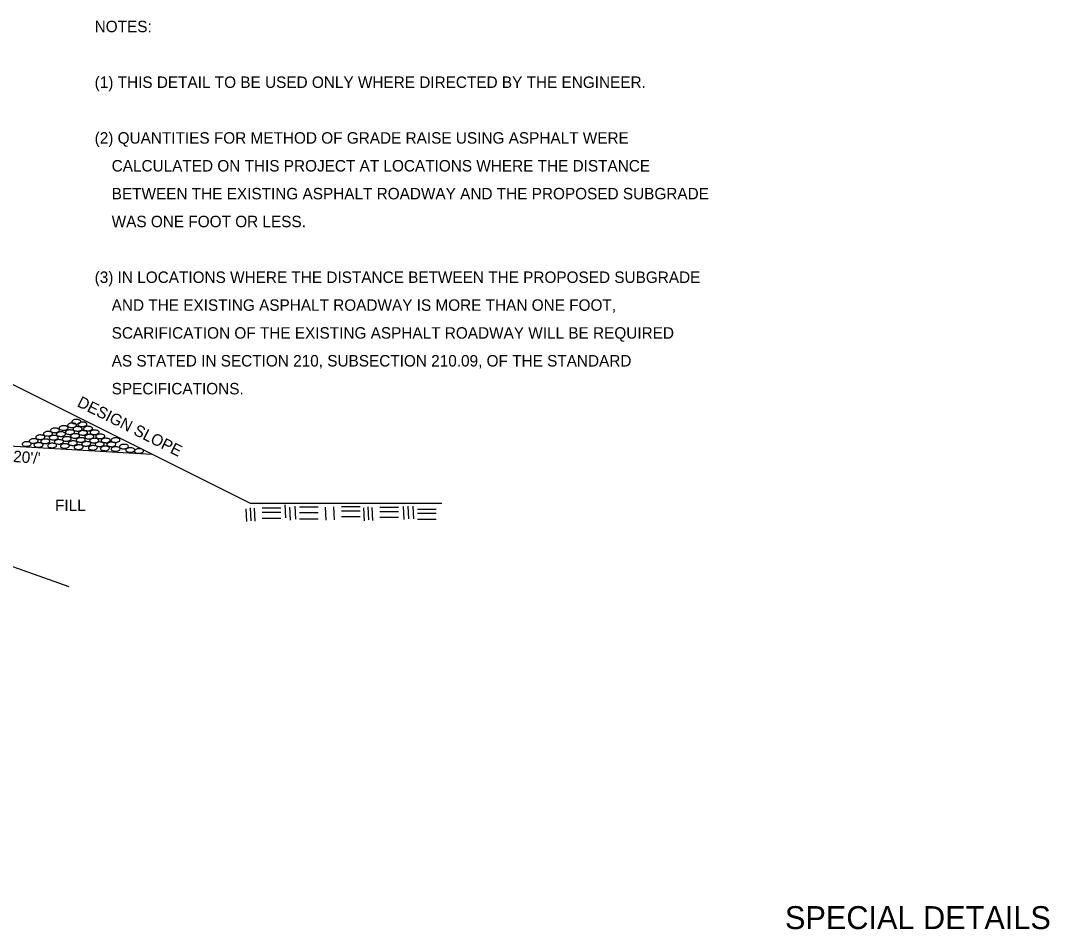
# Model space of a CAD drawing. Extents: x 1955771 to 1955918, y 566326 to 566544.
# Drawn here: x 1955864 to 1955917.8, y 566445.7 to 566493.2 of the extents above; entities that cross this region are included whole.
import ezdxf

# ---------------------------------------------------------------- set-up
doc = ezdxf.new("R2010")
doc.units = 0
doc.layers.add('R_Border', color=7, linetype='Continuous')
doc.layers.add('R_Logo', color=7, linetype='Continuous')

msp = doc.modelspace()

# ---------------------------------------------------------------- linework, layer by layer
at = {"layer": 'R_Logo'}
for p, q in [((1955876.008, 566467.953), (1955863.589, 566474.161)), ((1955855.453, 566471.441), (1955870.832, 566470.54)), ((1955849.109, 566469.803), (1955866.493, 566463.617)), ((1955886.016, 566467.953), (1955876.008, 566467.953)), ((1955877.804, 566467.882), (1955877.84, 566467.206)), ((1955878.033, 566467.767), (1955878.071, 566467.09)), ((1955878.322, 566467.826), (1955878.359, 566467.148)), ((1955879.546, 566467.769), (1955878.562, 566467.769)), ((1955879.908, 566467.76), (1955879.948, 566467.083)), ((1955880.343, 566467.784), (1955880.381, 566467.108)), ((1955881.736, 566467.784), (1955880.758, 566467.784)), ((1955882.146, 566467.778), (1955882.182, 566467.1)), ((1955882.348, 566467.754), (1955882.386, 566467.076)), ((1955883.741, 566467.754), (1955882.763, 566467.754)), ((1955883.989, 566467.802), (1955884.026, 566467.126)), ((1955884.231, 566467.828), (1955884.269, 566467.152)), ((1955884.488, 566467.828), (1955884.526, 566467.152)), ((1955875.754, 566467.687), (1955875.793, 566467.009)), ((1955875.987, 566467.732), (1955876.026, 566467.055)), ((1955876.19, 566467.71), (1955876.226, 566467.033)), ((1955877.583, 566467.71), (1955876.603, 566467.71)), ((1955877.583, 566467.485), (1955876.603, 566467.485)), ((1955879.546, 566467.478), (1955878.562, 566467.478)), ((1955881.736, 566467.558), (1955880.758, 566467.558)), ((1955881.736, 566467.256), (1955880.758, 566467.256)), ((1955881.912, 566467.73), (1955881.951, 566467.054)), ((1955883.741, 566467.53), (1955882.763, 566467.53)), ((1955883.741, 566467.228), (1955882.763, 566467.228)), ((1955885.717, 566467.652), (1955884.738, 566467.652)), ((1955885.717, 566467.429), (1955884.738, 566467.429)), ((1955877.583, 566467.183), (1955876.603, 566467.183)), ((1955879.546, 566467.133), (1955878.562, 566467.133)), ((1955885.717, 566467.125), (1955884.738, 566467.125))]:
    msp.add_line(p, q, dxfattribs=at)
for points in [[(1955866.663, 566471.931), (1955866.581, 566471.941), (1955866.481, 566471.967), (1955866.433, 566472.013), (1955866.426, 566472.042), (1955866.452, 566472.091), (1955866.478, 566472.115), (1955866.534, 566472.147), (1955866.612, 566472.166), (1955866.655, 566472.166), (1955866.717, 566472.16), (1955866.788, 566472.156), (1955866.84, 566472.135), (1955866.887, 566472.089), (1955866.896, 566472.06), (1955866.881, 566472.012), (1955866.844, 566471.984), (1955866.807, 566471.964), (1955866.749, 566471.942), (1955866.717, 566471.932), (1955866.663, 566471.931)], [(1955866.887, 566472.117), (1955866.804, 566472.127), (1955866.707, 566472.152), (1955866.659, 566472.202), (1955866.652, 566472.228), (1955866.676, 566472.279), (1955866.7, 566472.302), (1955866.757, 566472.332), (1955866.837, 566472.352), (1955866.879, 566472.352), (1955866.942, 566472.349), (1955867.01, 566472.344), (1955867.063, 566472.317), (1955867.116, 566472.277), (1955867.124, 566472.241), (1955867.109, 566472.199), (1955867.07, 566472.166), (1955867.032, 566472.152), (1955866.976, 566472.131), (1955866.942, 566472.118), (1955866.887, 566472.117)], [(1955867.205, 566471.982), (1955867.124, 566471.992), (1955867.023, 566472.016), (1955866.974, 566472.065), (1955866.967, 566472.09), (1955866.993, 566472.144), (1955867.021, 566472.164), (1955867.076, 566472.195), (1955867.154, 566472.217), (1955867.195, 566472.217), (1955867.26, 566472.211), (1955867.328, 566472.207), (1955867.382, 566472.181), (1955867.43, 566472.14), (1955867.439, 566472.105), (1955867.423, 566472.064), (1955867.387, 566472.029), (1955867.347, 566472.013), (1955867.293, 566471.995), (1955867.26, 566471.984), (1955867.205, 566471.982)], [(1955865.004, 566471.307), (1955864.92, 566471.317), (1955864.824, 566471.344), (1955864.777, 566471.392), (1955864.768, 566471.419), (1955864.793, 566471.471), (1955864.816, 566471.493), (1955864.873, 566471.522), (1955864.954, 566471.545), (1955864.995, 566471.545), (1955865.056, 566471.54), (1955865.127, 566471.534), (1955865.179, 566471.508), (1955865.232, 566471.467), (1955865.239, 566471.433), (1955865.224, 566471.389), (1955865.185, 566471.357), (1955865.15, 566471.342), (1955865.092, 566471.321), (1955865.056, 566471.309), (1955865.004, 566471.307)], [(1955865.406, 566471.488), (1955865.321, 566471.496), (1955865.223, 566471.523), (1955865.17, 566471.568), (1955865.165, 566471.598), (1955865.188, 566471.647), (1955865.22, 566471.671), (1955865.278, 566471.706), (1955865.356, 566471.721), (1955865.396, 566471.721), (1955865.457, 566471.718), (1955865.528, 566471.711), (1955865.58, 566471.691), (1955865.629, 566471.643), (1955865.635, 566471.615), (1955865.619, 566471.567), (1955865.582, 566471.539), (1955865.547, 566471.519), (1955865.495, 566471.502), (1955865.461, 566471.493), (1955865.406, 566471.488)], [(1955865.706, 566471.281), (1955865.619, 566471.292), (1955865.523, 566471.318), (1955865.474, 566471.365), (1955865.468, 566471.394), (1955865.493, 566471.444), (1955865.516, 566471.469), (1955865.575, 566471.497), (1955865.653, 566471.516), (1955865.694, 566471.516), (1955865.758, 566471.513), (1955865.828, 566471.508), (1955865.88, 566471.485), (1955865.931, 566471.44), (1955865.938, 566471.411), (1955865.922, 566471.361), (1955865.885, 566471.335), (1955865.846, 566471.317), (1955865.791, 566471.295), (1955865.758, 566471.282), (1955865.706, 566471.281)], [(1955865.764, 566471.661), (1955865.681, 566471.67), (1955865.582, 566471.704), (1955865.534, 566471.745), (1955865.525, 566471.775), (1955865.552, 566471.825), (1955865.58, 566471.851), (1955865.632, 566471.879), (1955865.711, 566471.898), (1955865.755, 566471.898), (1955865.817, 566471.901), (1955865.885, 566471.887), (1955865.941, 566471.862), (1955865.99, 566471.821), (1955865.997, 566471.789), (1955865.985, 566471.742), (1955865.945, 566471.71), (1955865.91, 566471.698), (1955865.85, 566471.678), (1955865.817, 566471.666), (1955865.764, 566471.661)], [(1955866.086, 566471.466), (1955866.003, 566471.475), (1955865.906, 566471.502), (1955865.855, 566471.55), (1955865.846, 566471.574), (1955865.873, 566471.63), (1955865.903, 566471.653), (1955865.953, 566471.685), (1955866.034, 566471.704), (1955866.077, 566471.704), (1955866.139, 566471.705), (1955866.21, 566471.694), (1955866.263, 566471.666), (1955866.312, 566471.627), (1955866.319, 566471.594), (1955866.305, 566471.548), (1955866.268, 566471.514), (1955866.229, 566471.498), (1955866.172, 566471.483), (1955866.139, 566471.471), (1955866.086, 566471.466)], [(1955866.225, 566471.789), (1955866.139, 566471.798), (1955866.041, 566471.827), (1955865.99, 566471.872), (1955865.985, 566471.903), (1955866.01, 566471.953), (1955866.037, 566471.977), (1955866.092, 566472.005), (1955866.172, 566472.024), (1955866.215, 566472.024), (1955866.278, 566472.021), (1955866.348, 566472.017), (1955866.398, 566471.994), (1955866.447, 566471.949), (1955866.455, 566471.919), (1955866.439, 566471.87), (1955866.401, 566471.842), (1955866.364, 566471.826), (1955866.311, 566471.803), (1955866.278, 566471.79), (1955866.225, 566471.789)], [(1955866.558, 566471.569), (1955866.473, 566471.58), (1955866.373, 566471.609), (1955866.32, 566471.653), (1955866.315, 566471.683), (1955866.342, 566471.732), (1955866.369, 566471.757), (1955866.43, 566471.788), (1955866.507, 566471.806), (1955866.547, 566471.806), (1955866.61, 566471.803), (1955866.678, 566471.795), (1955866.734, 566471.776), (1955866.779, 566471.728), (1955866.788, 566471.701), (1955866.772, 566471.651), (1955866.735, 566471.625), (1955866.698, 566471.605), (1955866.646, 566471.587), (1955866.612, 566471.576), (1955866.558, 566471.569)], [(1955866.824, 566471.373), (1955866.741, 566471.382), (1955866.643, 566471.411), (1955866.594, 566471.456), (1955866.588, 566471.485), (1955866.612, 566471.536), (1955866.636, 566471.559), (1955866.694, 566471.587), (1955866.773, 566471.609), (1955866.814, 566471.609), (1955866.877, 566471.605), (1955866.947, 566471.599), (1955867, 566471.573), (1955867.052, 566471.531), (1955867.057, 566471.498), (1955867.044, 566471.453), (1955867.006, 566471.423), (1955866.968, 566471.409), (1955866.912, 566471.386), (1955866.877, 566471.374), (1955866.824, 566471.373)], [(1955866.959, 566471.744), (1955866.872, 566471.753), (1955866.774, 566471.779), (1955866.723, 566471.827), (1955866.717, 566471.854), (1955866.742, 566471.907), (1955866.77, 566471.928), (1955866.826, 566471.958), (1955866.906, 566471.98), (1955866.948, 566471.98), (1955867.01, 566471.974), (1955867.08, 566471.97), (1955867.131, 566471.942), (1955867.181, 566471.903), (1955867.189, 566471.867), (1955867.173, 566471.825), (1955867.134, 566471.791), (1955867.099, 566471.778), (1955867.044, 566471.757), (1955867.01, 566471.745), (1955866.959, 566471.744)], [(1955867.238, 566471.531), (1955867.154, 566471.543), (1955867.055, 566471.567), (1955867.006, 566471.616), (1955866.998, 566471.642), (1955867.023, 566471.696), (1955867.052, 566471.715), (1955867.109, 566471.748), (1955867.188, 566471.77), (1955867.229, 566471.77), (1955867.29, 566471.763), (1955867.361, 566471.759), (1955867.412, 566471.733), (1955867.463, 566471.692), (1955867.471, 566471.657), (1955867.456, 566471.615), (1955867.416, 566471.583), (1955867.381, 566471.564), (1955867.324, 566471.548), (1955867.29, 566471.534), (1955867.238, 566471.531)], [(1955867.505, 566471.761), (1955867.417, 566471.77), (1955867.322, 566471.792), (1955867.268, 566471.843), (1955867.263, 566471.869), (1955867.289, 566471.921), (1955867.318, 566471.942), (1955867.374, 566471.975), (1955867.454, 566471.996), (1955867.493, 566471.996), (1955867.557, 566471.992), (1955867.626, 566471.987), (1955867.679, 566471.96), (1955867.725, 566471.919), (1955867.734, 566471.886), (1955867.719, 566471.841), (1955867.683, 566471.809), (1955867.645, 566471.791), (1955867.59, 566471.775), (1955867.557, 566471.763), (1955867.505, 566471.761)], [(1955867.558, 566471.571), (1955867.645, 566471.562), (1955867.743, 566471.536), (1955867.795, 566471.488), (1955867.801, 566471.46), (1955867.776, 566471.412), (1955867.747, 566471.387), (1955867.689, 566471.356), (1955867.611, 566471.337), (1955867.569, 566471.337), (1955867.508, 566471.342), (1955867.437, 566471.345), (1955867.386, 566471.369), (1955867.337, 566471.414), (1955867.33, 566471.444), (1955867.344, 566471.49), (1955867.384, 566471.519), (1955867.417, 566471.539), (1955867.474, 566471.559), (1955867.508, 566471.568), (1955867.558, 566471.571)], [(1955867.835, 566471.803), (1955867.916, 566471.792), (1955868.016, 566471.77), (1955868.069, 566471.72), (1955868.076, 566471.695), (1955868.052, 566471.641), (1955868.022, 566471.622), (1955867.964, 566471.585), (1955867.886, 566471.567), (1955867.844, 566471.567), (1955867.784, 566471.573), (1955867.712, 566471.577), (1955867.659, 566471.602), (1955867.613, 566471.644), (1955867.607, 566471.678), (1955867.622, 566471.721), (1955867.655, 566471.754), (1955867.692, 566471.773), (1955867.747, 566471.788), (1955867.782, 566471.801), (1955867.835, 566471.803)], [(1955868.136, 566471.593), (1955868.22, 566471.584), (1955868.319, 566471.559), (1955868.372, 566471.509), (1955868.378, 566471.484), (1955868.352, 566471.431), (1955868.325, 566471.411), (1955868.266, 566471.375), (1955868.19, 566471.357), (1955868.146, 566471.357), (1955868.083, 566471.361), (1955868.011, 566471.366), (1955867.962, 566471.393), (1955867.913, 566471.433), (1955867.907, 566471.469), (1955867.923, 566471.512), (1955867.958, 566471.545), (1955867.994, 566471.56), (1955868.051, 566471.577), (1955868.081, 566471.591), (1955868.136, 566471.593)], [(1955864.288, 566470.952), (1955864.205, 566470.959), (1955864.108, 566470.984), (1955864.061, 566471.034), (1955864.052, 566471.06), (1955864.079, 566471.114), (1955864.103, 566471.135), (1955864.159, 566471.167), (1955864.239, 566471.187), (1955864.279, 566471.187), (1955864.344, 566471.183), (1955864.414, 566471.177), (1955864.468, 566471.152), (1955864.515, 566471.111), (1955864.524, 566471.077), (1955864.508, 566471.032), (1955864.474, 566471.001), (1955864.431, 566470.982), (1955864.377, 566470.964), (1955864.344, 566470.954), (1955864.288, 566470.952)], [(1955864.657, 566471.114), (1955864.572, 566471.12), (1955864.478, 566471.148), (1955864.426, 566471.194), (1955864.42, 566471.223), (1955864.446, 566471.274), (1955864.472, 566471.297), (1955864.527, 566471.328), (1955864.605, 566471.348), (1955864.647, 566471.348), (1955864.712, 566471.344), (1955864.783, 566471.34), (1955864.832, 566471.314), (1955864.883, 566471.272), (1955864.892, 566471.239), (1955864.876, 566471.193), (1955864.84, 566471.164), (1955864.799, 566471.146), (1955864.742, 566471.124), (1955864.712, 566471.114), (1955864.657, 566471.114)], [(1955864.912, 566470.903), (1955864.826, 566470.911), (1955864.728, 566470.938), (1955864.679, 566470.984), (1955864.671, 566471.014), (1955864.701, 566471.065), (1955864.721, 566471.089), (1955864.783, 566471.117), (1955864.86, 566471.137), (1955864.9, 566471.137), (1955864.964, 566471.133), (1955865.033, 566471.128), (1955865.086, 566471.105), (1955865.137, 566471.06), (1955865.146, 566471.03), (1955865.128, 566470.981), (1955865.092, 566470.955), (1955865.055, 566470.937), (1955864.996, 566470.914), (1955864.964, 566470.904), (1955864.912, 566470.903)], [(1955865.266, 566471.095), (1955865.181, 566471.103), (1955865.086, 566471.128), (1955865.037, 566471.177), (1955865.029, 566471.204), (1955865.055, 566471.256), (1955865.079, 566471.277), (1955865.136, 566471.309), (1955865.216, 566471.33), (1955865.254, 566471.33), (1955865.319, 566471.326), (1955865.388, 566471.321), (1955865.442, 566471.295), (1955865.493, 566471.252), (1955865.501, 566471.22), (1955865.485, 566471.175), (1955865.447, 566471.144), (1955865.41, 566471.126), (1955865.356, 566471.108), (1955865.319, 566471.096), (1955865.266, 566471.095)], [(1955865.621, 566470.874), (1955865.537, 566470.883), (1955865.44, 566470.909), (1955865.391, 566470.958), (1955865.385, 566470.982), (1955865.41, 566471.037), (1955865.435, 566471.057), (1955865.491, 566471.09), (1955865.57, 566471.111), (1955865.611, 566471.111), (1955865.676, 566471.107), (1955865.744, 566471.101), (1955865.796, 566471.075), (1955865.846, 566471.034), (1955865.855, 566470.999), (1955865.842, 566470.955), (1955865.802, 566470.922), (1955865.766, 566470.908), (1955865.707, 566470.888), (1955865.676, 566470.874), (1955865.621, 566470.874)], [(1955865.982, 566471.061), (1955865.895, 566471.072), (1955865.795, 566471.101), (1955865.744, 566471.145), (1955865.735, 566471.175), (1955865.762, 566471.225), (1955865.791, 566471.248), (1955865.848, 566471.28), (1955865.927, 566471.298), (1955865.969, 566471.298), (1955866.03, 566471.296), (1955866.1, 566471.289), (1955866.154, 566471.267), (1955866.201, 566471.221), (1955866.21, 566471.191), (1955866.193, 566471.144), (1955866.155, 566471.114), (1955866.119, 566471.097), (1955866.067, 566471.081), (1955866.033, 566471.068), (1955865.982, 566471.061)], [(1955866.285, 566471.082), (1955866.365, 566471.081), (1955866.466, 566471.045), (1955866.515, 566470.999), (1955866.523, 566470.972), (1955866.498, 566470.918), (1955866.467, 566470.899), (1955866.415, 566470.871), (1955866.332, 566470.849), (1955866.291, 566470.845), (1955866.229, 566470.85), (1955866.161, 566470.864), (1955866.109, 566470.885), (1955866.06, 566470.922), (1955866.053, 566470.957), (1955866.067, 566471.001), (1955866.105, 566471.032), (1955866.14, 566471.054), (1955866.195, 566471.072), (1955866.231, 566471.081), (1955866.285, 566471.082)], [(1955866.388, 566471.219), (1955866.305, 566471.228), (1955866.208, 566471.258), (1955866.158, 566471.302), (1955866.15, 566471.33), (1955866.176, 566471.38), (1955866.205, 566471.409), (1955866.256, 566471.435), (1955866.337, 566471.453), (1955866.378, 566471.453), (1955866.439, 566471.456), (1955866.51, 566471.444), (1955866.564, 566471.42), (1955866.614, 566471.375), (1955866.621, 566471.348), (1955866.607, 566471.298), (1955866.569, 566471.27), (1955866.531, 566471.252), (1955866.475, 566471.236), (1955866.439, 566471.223), (1955866.388, 566471.219)], [(1955866.697, 566471.231), (1955866.781, 566471.229), (1955866.881, 566471.194), (1955866.93, 566471.148), (1955866.938, 566471.118), (1955866.912, 566471.068), (1955866.882, 566471.045), (1955866.828, 566471.02), (1955866.744, 566470.997), (1955866.705, 566470.993), (1955866.643, 566471.001), (1955866.576, 566471.013), (1955866.522, 566471.034), (1955866.473, 566471.072), (1955866.466, 566471.105), (1955866.481, 566471.149), (1955866.519, 566471.179), (1955866.553, 566471.204), (1955866.61, 566471.221), (1955866.645, 566471.229), (1955866.697, 566471.231)], [(1955867.006, 566471.029), (1955867.089, 566471.019), (1955867.188, 566470.985), (1955867.237, 566470.944), (1955867.245, 566470.914), (1955867.217, 566470.866), (1955867.189, 566470.839), (1955867.134, 566470.808), (1955867.055, 566470.79), (1955867.014, 566470.79), (1955866.951, 566470.789), (1955866.882, 566470.799), (1955866.828, 566470.825), (1955866.779, 566470.868), (1955866.772, 566470.897), (1955866.788, 566470.946), (1955866.824, 566470.976), (1955866.862, 566470.992), (1955866.919, 566471.01), (1955866.951, 566471.022), (1955867.006, 566471.029)], [(1955867.114, 566471.402), (1955867.195, 566471.399), (1955867.298, 566471.363), (1955867.345, 566471.318), (1955867.353, 566471.289), (1955867.327, 566471.239), (1955867.3, 566471.216), (1955867.245, 566471.191), (1955867.163, 566471.169), (1955867.122, 566471.166), (1955867.059, 566471.172), (1955866.993, 566471.183), (1955866.938, 566471.2), (1955866.889, 566471.242), (1955866.882, 566471.272), (1955866.896, 566471.319), (1955866.936, 566471.349), (1955866.971, 566471.374), (1955867.025, 566471.392), (1955867.06, 566471.399), (1955867.114, 566471.402)], [(1955867.402, 566471.197), (1955867.485, 566471.191), (1955867.586, 566471.161), (1955867.636, 566471.116), (1955867.645, 566471.089), (1955867.619, 566471.037), (1955867.59, 566471.014), (1955867.533, 566470.977), (1955867.456, 566470.964), (1955867.412, 566470.964), (1955867.349, 566470.966), (1955867.281, 566470.972), (1955867.229, 566470.997), (1955867.181, 566471.041), (1955867.173, 566471.072), (1955867.189, 566471.117), (1955867.226, 566471.148), (1955867.263, 566471.166), (1955867.316, 566471.183), (1955867.348, 566471.193), (1955867.402, 566471.197)], [(1955867.751, 566470.992), (1955867.836, 566470.981), (1955867.934, 566470.958), (1955867.983, 566470.909), (1955867.99, 566470.882), (1955867.962, 566470.832), (1955867.937, 566470.808), (1955867.879, 566470.779), (1955867.801, 566470.756), (1955867.761, 566470.756), (1955867.7, 566470.76), (1955867.629, 566470.768), (1955867.576, 566470.79), (1955867.525, 566470.835), (1955867.518, 566470.866), (1955867.533, 566470.911), (1955867.57, 566470.942), (1955867.609, 566470.959), (1955867.665, 566470.977), (1955867.7, 566470.989), (1955867.751, 566470.992)], [(1955867.817, 566471.368), (1955867.902, 566471.361), (1955868.002, 566471.333), (1955868.055, 566471.284), (1955868.062, 566471.256), (1955868.034, 566471.204), (1955868.005, 566471.184), (1955867.947, 566471.158), (1955867.867, 566471.13), (1955867.825, 566471.13), (1955867.763, 566471.137), (1955867.695, 566471.145), (1955867.644, 566471.167), (1955867.597, 566471.209), (1955867.589, 566471.241), (1955867.605, 566471.285), (1955867.638, 566471.317), (1955867.673, 566471.337), (1955867.728, 566471.357), (1955867.763, 566471.365), (1955867.817, 566471.368)], [(1955868.104, 566471.178), (1955868.19, 566471.171), (1955868.288, 566471.142), (1955868.336, 566471.096), (1955868.343, 566471.067), (1955868.319, 566471.018), (1955868.289, 566470.992), (1955868.234, 566470.964), (1955868.155, 566470.943), (1955868.115, 566470.943), (1955868.052, 566470.949), (1955867.983, 566470.954), (1955867.93, 566470.977), (1955867.878, 566471.02), (1955867.872, 566471.049), (1955867.887, 566471.098), (1955867.927, 566471.126), (1955867.962, 566471.144), (1955868.016, 566471.167), (1955868.052, 566471.177), (1955868.104, 566471.178)], [(1955868.42, 566471.375), (1955868.504, 566471.366), (1955868.601, 566471.341), (1955868.653, 566471.294), (1955868.66, 566471.267), (1955868.631, 566471.214), (1955868.604, 566471.193), (1955868.549, 566471.162), (1955868.469, 566471.14), (1955868.428, 566471.14), (1955868.365, 566471.146), (1955868.296, 566471.151), (1955868.243, 566471.175), (1955868.195, 566471.219), (1955868.19, 566471.25), (1955868.201, 566471.295), (1955868.24, 566471.326), (1955868.275, 566471.344), (1955868.331, 566471.366), (1955868.368, 566471.374), (1955868.42, 566471.375)], [(1955868.715, 566471.168), (1955868.796, 566471.162), (1955868.899, 566471.13), (1955868.945, 566471.084), (1955868.952, 566471.054), (1955868.928, 566471.004), (1955868.904, 566470.98), (1955868.846, 566470.957), (1955868.767, 566470.931), (1955868.726, 566470.931), (1955868.66, 566470.937), (1955868.594, 566470.947), (1955868.54, 566470.967), (1955868.491, 566471.009), (1955868.481, 566471.043), (1955868.499, 566471.087), (1955868.534, 566471.117), (1955868.575, 566471.137), (1955868.626, 566471.158), (1955868.66, 566471.167), (1955868.715, 566471.168)], [(1955868.936, 566471.158), (1955868.853, 566471.167), (1955868.755, 566471.193), (1955868.707, 566471.24), (1955868.698, 566471.268), (1955868.726, 566471.319), (1955868.75, 566471.342), (1955868.807, 566471.371), (1955868.884, 566471.393), (1955868.928, 566471.393), (1955868.99, 566471.389), (1955869.06, 566471.383), (1955869.112, 566471.357), (1955869.163, 566471.315), (1955869.17, 566471.281), (1955869.155, 566471.238), (1955869.119, 566471.206), (1955869.08, 566471.192), (1955869.022, 566471.171), (1955868.99, 566471.158), (1955868.936, 566471.158)], [(1955869.373, 566471.056), (1955869.456, 566471.049), (1955869.555, 566471.019), (1955869.605, 566470.977), (1955869.612, 566470.952), (1955869.586, 566470.896), (1955869.561, 566470.868), (1955869.501, 566470.843), (1955869.424, 566470.826), (1955869.384, 566470.824), (1955869.32, 566470.824), (1955869.248, 566470.835), (1955869.2, 566470.859), (1955869.148, 566470.899), (1955869.14, 566470.931), (1955869.155, 566470.977), (1955869.193, 566471.012), (1955869.23, 566471.029), (1955869.287, 566471.045), (1955869.32, 566471.049), (1955869.373, 566471.056)], [(1955868.383, 566470.959), (1955868.469, 566470.955), (1955868.565, 566470.921), (1955868.613, 566470.875), (1955868.621, 566470.845), (1955868.595, 566470.796), (1955868.571, 566470.775), (1955868.515, 566470.748), (1955868.436, 566470.72), (1955868.394, 566470.72), (1955868.331, 566470.728), (1955868.264, 566470.736), (1955868.208, 566470.756), (1955868.156, 566470.799), (1955868.148, 566470.832), (1955868.165, 566470.877), (1955868.201, 566470.908), (1955868.24, 566470.928), (1955868.296, 566470.951), (1955868.331, 566470.958), (1955868.383, 566470.959)], [(1955868.944, 566470.926), (1955869.025, 566470.924), (1955869.126, 566470.893), (1955869.171, 566470.847), (1955869.18, 566470.822), (1955869.155, 566470.766), (1955869.13, 566470.744), (1955869.075, 566470.714), (1955868.994, 566470.696), (1955868.948, 566470.691), (1955868.889, 566470.699), (1955868.821, 566470.711), (1955868.766, 566470.728), (1955868.716, 566470.77), (1955868.707, 566470.799), (1955868.725, 566470.845), (1955868.76, 566470.88), (1955868.798, 566470.902), (1955868.855, 566470.915), (1955868.89, 566470.924), (1955868.944, 566470.926)], [(1955869.712, 566470.88), (1955869.796, 566470.871), (1955869.892, 566470.841), (1955869.939, 566470.796), (1955869.948, 566470.77), (1955869.925, 566470.715), (1955869.898, 566470.691), (1955869.84, 566470.661), (1955869.76, 566470.645), (1955869.72, 566470.645), (1955869.657, 566470.646), (1955869.59, 566470.652), (1955869.536, 566470.679), (1955869.484, 566470.718), (1955869.476, 566470.754), (1955869.49, 566470.798), (1955869.53, 566470.831), (1955869.566, 566470.845), (1955869.623, 566470.864), (1955869.659, 566470.874), (1955869.712, 566470.88)], [(1955870.167, 566470.584), (1955870.081, 566470.591), (1955869.984, 566470.618), (1955869.935, 566470.666), (1955869.929, 566470.694), (1955869.956, 566470.747), (1955869.978, 566470.769), (1955870.036, 566470.796), (1955870.116, 566470.821), (1955870.158, 566470.821), (1955870.219, 566470.816), (1955870.289, 566470.81), (1955870.341, 566470.784), (1955870.392, 566470.743), (1955870.398, 566470.711), (1955870.386, 566470.663), (1955870.349, 566470.634), (1955870.311, 566470.616), (1955870.253, 566470.595), (1955870.219, 566470.585), (1955870.167, 566470.584)]]:
    msp.add_spline(points, degree=3, dxfattribs=at)

# ---------------------------------------------------------------- texts
at = {"layer": 'R_Border'}
msp.add_text('SPECIAL DETAILS', height=1.2, rotation=0, dxfattribs=at).set_placement((1955903.968, 566445.698))
at = {"layer": 'R_Logo'}
for s, p in [('NOTES:', (1955867.845, 566492.61)), ('(1) THIS DETAIL TO BE USED ONLY WHERE DIRECTED BY THE ENGINEER.', (1955867.845, 566489.695)), ('(2) QUANTITIES FOR METHOD OF GRADE RAISE USING ASPHALT WERE', (1955867.845, 566486.781)), ('    CALCULATED ON THIS PROJECT AT LOCATIONS WHERE THE DISTANCE', (1955867.845, 566485.324)), ('    BETWEEN THE EXISTING ASPHALT ROADWAY AND THE PROPOSED SUBGRADE', (1955867.845, 566483.867)), ('    WAS ONE FOOT OR LESS.', (1955867.845, 566482.41)), ('(3) IN LOCATIONS WHERE THE DISTANCE BETWEEN THE PROPOSED SUBGRADE', (1955867.845, 566479.495)), ('    AND THE EXISTING ASPHALT ROADWAY IS MORE THAN ONE FOOT,', (1955867.845, 566478.038)), ('    SCARIFICATION OF THE EXISTING ASPHALT ROADWAY WILL BE REQUIRED', (1955867.845, 566476.581)), ('    AS STATED IN SECTION 210, SUBSECTION 210.09, OF THE STANDARD', (1955867.845, 566475.124)), ('    SPECIFICATIONS.', (1955867.845, 566473.667)), ('FILL', (1955865.772, 566467.563))]:
    msp.add_text(s, height=0.6, dxfattribs=at).set_placement(p)
for s, rotation, p in [('DESIGN SLOPE', 333.435, (1955866.883, 566473.065)), ("0.020'/'", 355.6232, (1955862.451, 566470.218))]:
    msp.add_text(s, height=0.6, rotation=rotation, dxfattribs=at).set_placement(p)

doc.saveas('drawing.dxf')
